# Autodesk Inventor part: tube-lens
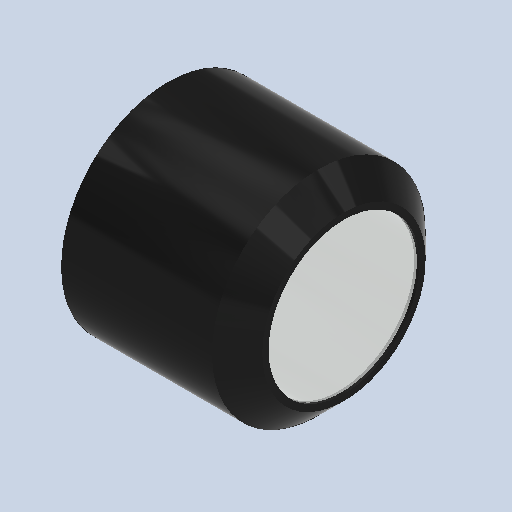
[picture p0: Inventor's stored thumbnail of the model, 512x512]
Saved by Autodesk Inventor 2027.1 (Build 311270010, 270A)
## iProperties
Created: 2026-07
Part Number: tube-lens
Material: Generic
Document SubType Name: Modeling
Designer: dunge
Density: 1 g/cm^3
Appearance: Default
Author: dunge
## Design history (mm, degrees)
derived "scan-lens-sl-simple.ipt"
  workaxis "Work Axis1"
  workpoint "Work Point1"
feature "Solid1::scan-lens-sl-simple.ipt"
tag "TaggingFeature1"
node "Finishes"
body "Solid1"
node "Finish1" dims "Finish1_Area" = 1208.24684
node "Finish2" dims "Finish2_Area" = 291.86351
other parameters: "d4" = 0.508, "LIGHT_RADIUS" = 15.24, "d9" = 135 deg, "d10" = 0.508, "BODY_SIZE" = 35.56, "d12" = 5.08, "d13" = 0.508, "d14" = 0.508, "d15" = 0, "d16" = 0, "d18" = 21.59
